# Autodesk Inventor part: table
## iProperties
Author: ajt
Created: 2001-10
Part Number: table
Material: Par défaut
Document SubType Name: Proxy Part
Designer: ajt
Control State: 0
Master: False
Checked Out: False
PropertySet Name: Design Tracking Control
Shininess: 21.0
PropertySet Name: _Private Model Information
Length Units: 11269
Angle Units: 11283
Time Units: 11279
Mass Units: 11290
Length Display Precision: 3
Angle Display Precision: 2
Compacted: False
Density: 0.0
Volumn: 0.0
Area: 0.0
PropertySet Name: Model Information
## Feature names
1. LinkedPart1
